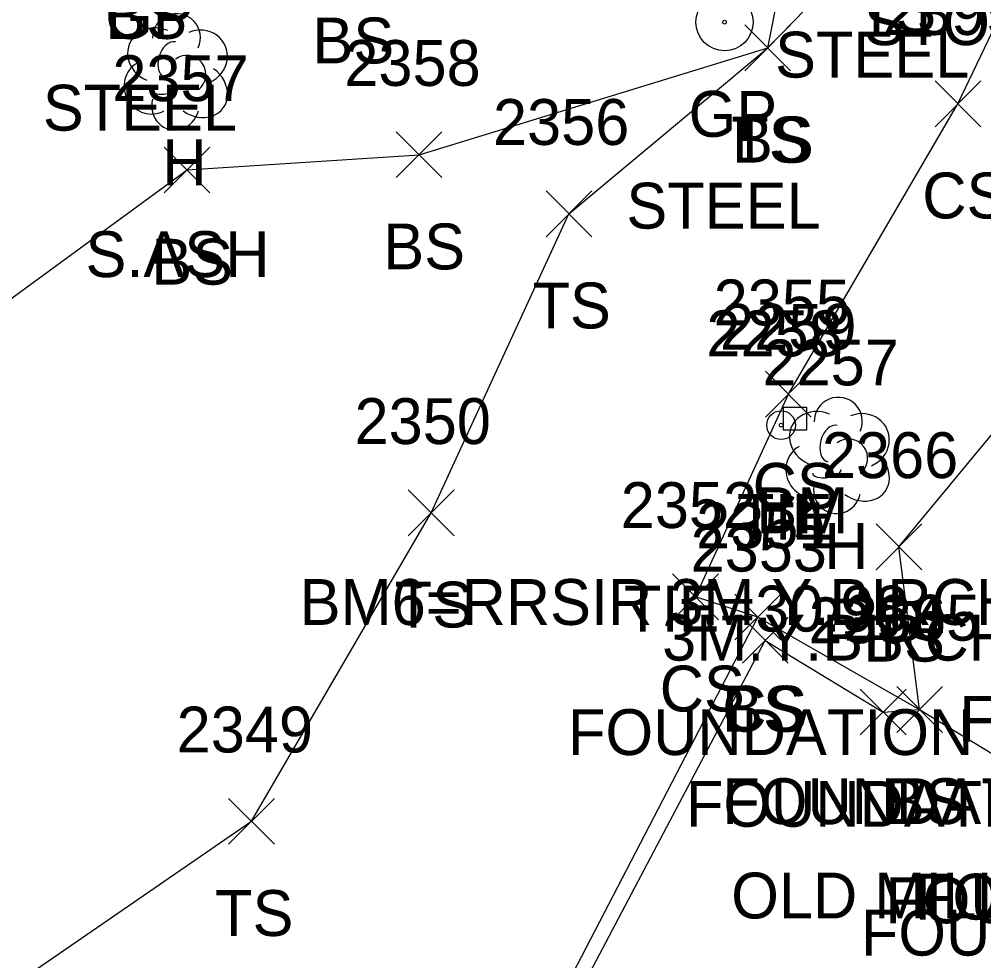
# Model space of a CAD drawing. Extents: x 1512665 to 1513714, y 110636 to 112816.
# Drawn here: x 1513001.68 to 1513043.75, y 110699.18 to 110740.23 of the extents above; entities that cross this region are included whole.
import ezdxf

# ---------------------------------------------------------------- set-up
doc = ezdxf.new("R2010")
doc.units = 0
for name, color, linetype in [('C_A', 7, 'Continuous'), ('C_C', 7, 'Continuous'), ('C_I', 7, 'Continuous'), ('CBP', 7, 'Continuous'), ('CPBM', 7, 'Continuous'), ('L_A', 7, 'Continuous'), ('L_C', 7, 'Continuous'), ('L_I', 7, 'Continuous'), ('L_TIC', 7, 'Continuous'), ('LBC', 7, 'Continuous'), ('LELB', 7, 'Continuous'), ('LTD', 7, 'Continuous'), ('R_A', 7, 'Continuous'), ('R_C', 7, 'Continuous'), ('RGP', 7, 'Continuous')]:
    doc.layers.add(name, color=color, linetype=linetype)

msp = doc.modelspace()

# ---------------------------------------------------------------- linework, layer by layer
at = {"layer": 'CBP'}
for radius in [0.625, 0.0833]:
    msp.add_circle((1513034.916, 110722.535), radius, dxfattribs=at)
at = {"layer": 'CPBM'}
for p, q in [((1513035.018, 110722.323), (1513035.018, 110723.323)), ((1513035.018, 110723.323), (1513036.018, 110723.323)), ((1513036.018, 110723.323), (1513036.018, 110722.323)), ((1513035.52, 110722.824), (1513035.52, 110722.824)), ((1513035.52, 110722.824), (1513035.52, 110722.824)), ((1513036.018, 110722.323), (1513035.018, 110722.323))]:
    msp.add_line(p, q, dxfattribs=at)
at = {"layer": 'L_TIC'}
for points in [[(1513033.332, 110737.983), (1513035.332, 110739.983)], [(1513035.332, 110737.983), (1513033.332, 110739.983)], [(1513033.332, 110737.983), (1513035.332, 110739.983)], [(1513035.332, 110737.983), (1513033.332, 110739.983)], [(1513041.631, 110735.547), (1513043.631, 110737.547)], [(1513043.631, 110735.547), (1513041.631, 110737.547)], [(1513018.12, 110733.326), (1513020.12, 110735.326)], [(1513020.12, 110733.326), (1513018.12, 110735.326)], [(1513008, 110732.662), (1513010, 110734.662)], [(1513010, 110732.662), (1513008, 110734.662)], [(1513024.66, 110730.752), (1513026.66, 110732.752)], [(1513026.66, 110730.752), (1513024.66, 110732.752)], [(1513034.232, 110722.885), (1513036.232, 110724.885)], [(1513036.232, 110722.885), (1513034.232, 110724.885)], [(1513018.652, 110717.711), (1513020.652, 110719.711)], [(1513020.652, 110717.711), (1513018.652, 110719.711)], [(1513039.055, 110716.226), (1513041.055, 110718.226)], [(1513041.055, 110716.226), (1513039.055, 110718.226)], [(1513030.178, 110714.049), (1513032.178, 110716.049)], [(1513032.178, 110714.049), (1513030.178, 110716.049)], [(1513032.901, 110713.169), (1513034.901, 110715.169)], [(1513034.901, 110713.169), (1513032.901, 110715.169)], [(1513032.901, 110713.169), (1513034.901, 110715.169)], [(1513034.901, 110713.169), (1513032.901, 110715.169)], [(1513033.225, 110712.151), (1513035.225, 110714.151)], [(1513035.225, 110712.151), (1513033.225, 110714.151)], [(1513039.959, 110709.138), (1513041.959, 110711.138)], [(1513041.959, 110709.138), (1513039.959, 110711.138)], [(1513039.959, 110709.138), (1513041.959, 110711.138)], [(1513041.959, 110709.138), (1513039.959, 110711.138)], [(1513038.368, 110709.025), (1513040.368, 110711.025)], [(1513040.368, 110709.025), (1513038.368, 110711.025)], [(1513010.814, 110704.262), (1513012.814, 110706.262)], [(1513012.814, 110704.262), (1513010.814, 110706.262)]]:
    msp.add_lwpolyline(points, dxfattribs=at)
at = {"layer": 'LBC'}
msp.add_lwpolyline([(1513045.304, 110650.287), (1513027.487, 110660.038), (1513013.218, 110667.913), (1513012.214, 110669.098), (1513010.961, 110669.569), (1513018.401, 110683.181), (1513034.225, 110713.151), (1513039.368, 110710.025), (1513040.959, 110710.138), (1513048.066, 110705.816), (1513054.516, 110701.992), (1513054.311, 110701.401), (1513047.001, 110704.407)], dxfattribs=at)
at = {"layer": 'LELB'}
for points in [[(1513018.15, 110683.845), (1513008.389, 110681.438), (1512992.529, 110692.019), (1513011.814, 110705.262), (1513019.652, 110718.711), (1513025.66, 110731.752), (1513034.332, 110738.983), (1513039.854, 110744.651), (1513044.439, 110751.049), (1513044.971, 110754.973), (1513045.977, 110758.546)], [(1513013.218, 110667.913), (1513010.024, 110669.518), (1513018.15, 110683.845), (1513033.901, 110714.169), (1513040.959, 110710.138), (1513040.055, 110717.226), (1513047.05, 110725.671), (1513052.118, 110732.903), (1513052.004, 110737.788), (1513054.843, 110746.139), (1513051.861, 110747.033), (1513047.946, 110747.666), (1513048.845, 110752.609)], [(1512977.643, 110679.977), (1512992.529, 110692.019), (1512998.215, 110725.784), (1513009, 110733.662), (1513019.12, 110734.326), (1513034.332, 110738.983), (1513036.177, 110748.289), (1513044.439, 110751.049)], [(1513033.901, 110714.169), (1513031.178, 110715.049), (1513035.232, 110723.885), (1513042.631, 110736.547), (1513047.946, 110747.666)]]:
    msp.add_lwpolyline(points, dxfattribs=at)
at = {"layer": 'LTD'}
for p, q in [((1513008.492, 110737.991), (1513008.492, 110737.991)), ((1513008.492, 110737.991), (1513008.492, 110737.991)), ((1513037.363, 110721.268), (1513037.363, 110721.268)), ((1513037.363, 110721.268), (1513037.363, 110721.268))]:
    msp.add_line(p, q, dxfattribs=at)
for centre in [(1513008.539, 110739.425), (1513037.41, 110722.702)]:
    msp.add_arc(centre, 1.047, 335.5272, 180.9563, dxfattribs=at)
for centre, major_axis, ratio, start_param, end_param in [((1513007.7, 110738.658), (1.21, -0.512), 0.895232, 1.570796, 4.712389), ((1513009.534, 110738.575), (-1.141, -0.483), 0.949671, 1.570796, 4.712389), ((1513008.284, 110738.449), (-0.208, -0.792), 0.645439, 3.141593, 6.283185), ((1513008.992, 110737.824), (-0.5, 0.667), 0.989748, 3.141593, 6.283185), ((1513007.409, 110737.282), (0.584, -1.042), 0.959034, 3.141593, 6.283185), ((1513009.492, 110737.158), (-1.09, 0.792), 0.841452, 1.570796, 4.712389), ((1513008.034, 110737.241), (-0.625, -0.083), 0.423636, 0, 3.141593), ((1513008.492, 110736.491), (0.265, 1.061), 0.942809, 1.570796, 4.712389), ((1513036.571, 110721.934), (1.21, -0.512), 0.895232, 1.570796, 4.712389), ((1513038.405, 110721.851), (-1.141, -0.483), 0.949671, 1.570796, 4.712389), ((1513037.155, 110721.726), (-0.208, -0.792), 0.645439, 3.141593, 6.283185), ((1513037.863, 110721.101), (-0.5, 0.667), 0.989748, 3.141593, 6.283185), ((1513036.28, 110720.559), (0.584, -1.042), 0.959034, 3.141593, 6.283185), ((1513038.363, 110720.435), (-1.09, 0.792), 0.841452, 1.570796, 4.712389), ((1513036.905, 110720.518), (-0.625, -0.083), 0.423636, 0, 3.141593), ((1513037.363, 110719.768), (0.265, 1.061), 0.942809, 1.570796, 4.712389)]:
    msp.add_ellipse(centre, major_axis=major_axis, ratio=ratio, start_param=start_param, end_param=end_param, dxfattribs=at)
at = {"layer": 'RGP'}
msp.add_line((1513032.449, 110740.105), (1513032.449, 110740.105), dxfattribs=at)
for radius in [1.25, 0.0833]:
    msp.add_circle((1513032.449, 110740.105), radius, dxfattribs=at)

# ---------------------------------------------------------------- texts
at = {"layer": 'C_A'}
for s, p in [('TIE', (1513032.994, 110717.535)), ('BM', (1513033.835, 110717.824))]:
    msp.add_text(s, height=2, dxfattribs=at).set_placement(p)
at = {"layer": 'C_C'}
for s, p in [('BM6=RRSIR 3M.Y.BIRCH, ELEV:', (1513013.914, 110713.824)), ('TIE=30.98', (1513028.065, 110713.535))]:
    msp.add_text(s, height=2, dxfattribs=at).set_placement(p)
at = {"layer": 'C_I'}
for s, p in [('2258', (1513031.656, 110725.535)), ('2259', (1513032.253, 110725.824))]:
    msp.add_text(s, height=2, dxfattribs=at).set_placement(p)
at = {"layer": 'L_A'}
for s, p in [('BS', (1513005.433, 110739.376)), ('TS', (1513038.264, 110739.651)), ('BS', (1513014.47, 110738.308)), ('TS', (1513032.741, 110733.983)), ('BS', (1513032.773, 110733.983)), ('H', (1513007.925, 110732.991)), ('CS', (1513041.072, 110731.547)), ('BS', (1513017.561, 110729.326)), ('BS', (1513007.441, 110728.662)), ('TS', (1513024.07, 110726.752)), ('CS', (1513033.673, 110718.885)), ('H', (1513036.796, 110716.268)), ('TS', (1513018.061, 110713.711)), ('BS', (1513038.496, 110712.226)), ('CS', (1513029.619, 110710.049)), ('CS', (1513032.342, 110709.169)), ('BS', (1513032.342, 110709.169)), ('FOUNDATION', (1513042.694, 110708.73)), ('FOUNDATION', (1513025.619, 110708.151)), ('FOUNDATION', (1513030.762, 110705.025)), ('FOUNDATION', (1513032.352, 110705.138)), ('BS', (1513039.4, 110705.138)), ('FOUNDATION', (1513039.459, 110700.816)), ('FOUNDATION', (1513039.459, 110700.816)), ('FOUNDATION', (1513040.755, 110700.977)), ('TS', (1513010.224, 110700.262)), ('FOUNDATION', (1513038.395, 110699.407))]:
    msp.add_text(s, height=2, dxfattribs=at).set_placement(p)
at = {"layer": 'L_C'}
for s, p in [('STONE WING', (1513038.528, 110739.103)), ('S.ASH', (1513004.571, 110728.991)), ('3M.Y.BIRCH', (1513029.725, 110712.268)), ('OLD MILL', (1513032.738, 110701.025))]:
    msp.add_text(s, height=2, dxfattribs=at).set_placement(p)
at = {"layer": 'L_I'}
for s, p in [('2399', (1513039.363, 110739.547)), ('2358', (1513015.86, 110737.326)), ('2357', (1513005.74, 110736.662)), ('2356', (1513022.345, 110734.752)), ('2355', (1513031.973, 110726.885)), ('2257', (1513034.103, 110724.268)), ('2350', (1513016.305, 110721.711)), ('2366', (1513036.693, 110720.226)), ('2352', (1513027.919, 110718.049)), ('2351', (1513031.208, 110717.169)), ('2351', (1513031.208, 110717.169)), ('2353', (1513030.965, 110716.151)), ('2354', (1513036.109, 110713.025)), ('2365', (1513037.652, 110713.138)), ('2365', (1513037.652, 110713.138)), ('2349', (1513008.546, 110708.262))]:
    msp.add_text(s, height=2, dxfattribs=at).set_placement(p)
at = {"layer": 'R_A'}
for p in [(1513005.425, 110739.376), (1513030.882, 110735.105)]:
    msp.add_text('GP', height=2, dxfattribs=at).set_placement(p)
at = {"layer": 'R_C'}
for p in [(1513034.652, 110737.689), (1513002.708, 110735.376), (1513028.165, 110731.105)]:
    msp.add_text('STEEL', height=2, dxfattribs=at).set_placement(p)

doc.saveas('drawing.dxf')
